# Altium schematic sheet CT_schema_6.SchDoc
size 251 x 159 mm
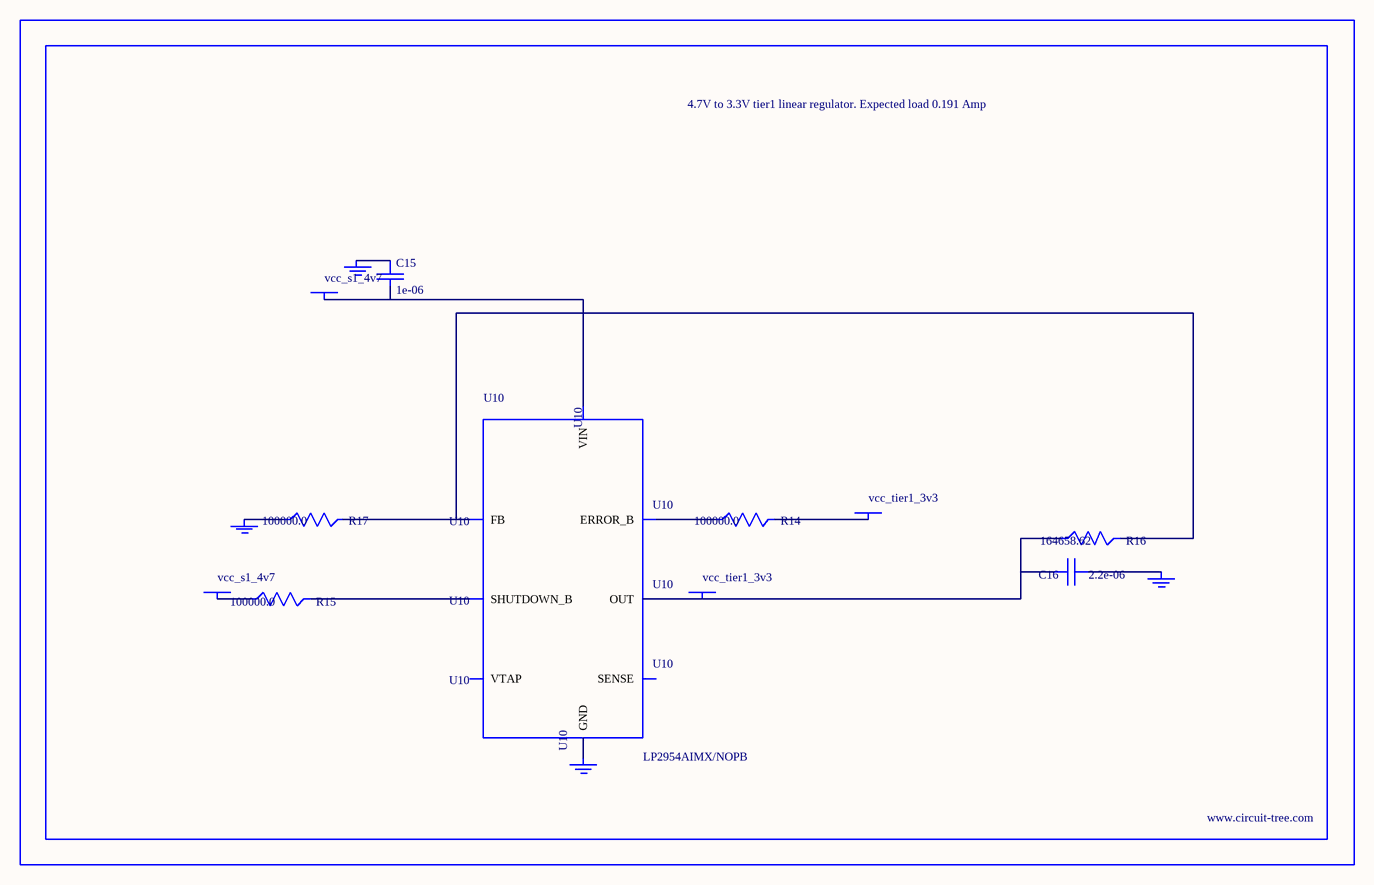
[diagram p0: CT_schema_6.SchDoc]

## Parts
BORDER5  (no value)
C15  1e-06  [EXV-9B]
C16  2.2e-06  [EXV-9B]
GND_INSTANCE_5_0  (no value)
GND_INSTANCE_5_1  (no value)
GND_INSTANCE_5_2  (no value)
GND_INSTANCE_5_3  (no value)
POWER_INSTANCE_5_0  vcc_s1_4v7
POWER_INSTANCE_5_1  vcc_tier1_3v3
POWER_INSTANCE_5_2  vcc_s1_4v7
POWER_INSTANCE_5_3  vcc_tier1_3v3
R14  100000.0  [R0603]
R15  100000.0  [R0603]
R16  164658.62  [R0603]
R17  100000.0  [R0603]
U10  LP2954AIMX/NOPB  [LP2954]

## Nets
NetC15_1: C15.1 GND_INSTANCE_5_2.0(GND)
NetC15_2: C15.2 POWER_INSTANCE_5_2.0(PWR) U10.8(VIN)
NetC16_1: C16.1 GND_INSTANCE_5_0.0(GND)
NetC16_2: C16.2 POWER_INSTANCE_5_3.0(PWR) R16.1 U10.1(OUT)
NetGND_INSTANCE_5_1_0: GND_INSTANCE_5_1.0(GND) R17.1
NetGND_INSTANCE_5_3_0: GND_INSTANCE_5_3.0(GND) U10.4(GND)
NetPOWER_INSTANCE_5_0_0: POWER_INSTANCE_5_0.0(PWR) R15.1
NetPOWER_INSTANCE_5_1_0: POWER_INSTANCE_5_1.0(PWR) R14.2
NetR14_1: R14.1 U10.5(ERROR_B)
NetR15_2: R15.2 U10.3(SHUTDOWN_B)
NetR16_2: R16.2 R17.2 U10.7(FB)

Not connected (* = marked no-connect by the designer): U10 2(SENSE) 6(VTAP)

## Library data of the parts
BORDER5 = BORDER_PAGE5
C15 = EDK105M050A9BAA
C16 = EDK225M050A9BAA
GND_INSTANCE_5_0-GND_INSTANCE_5_3 = GND
POWER_INSTANCE_5_0-POWER_INSTANCE_5_3 = PWR
R14 R15 R17 = RC0603JR-07100KL
R16 = R16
